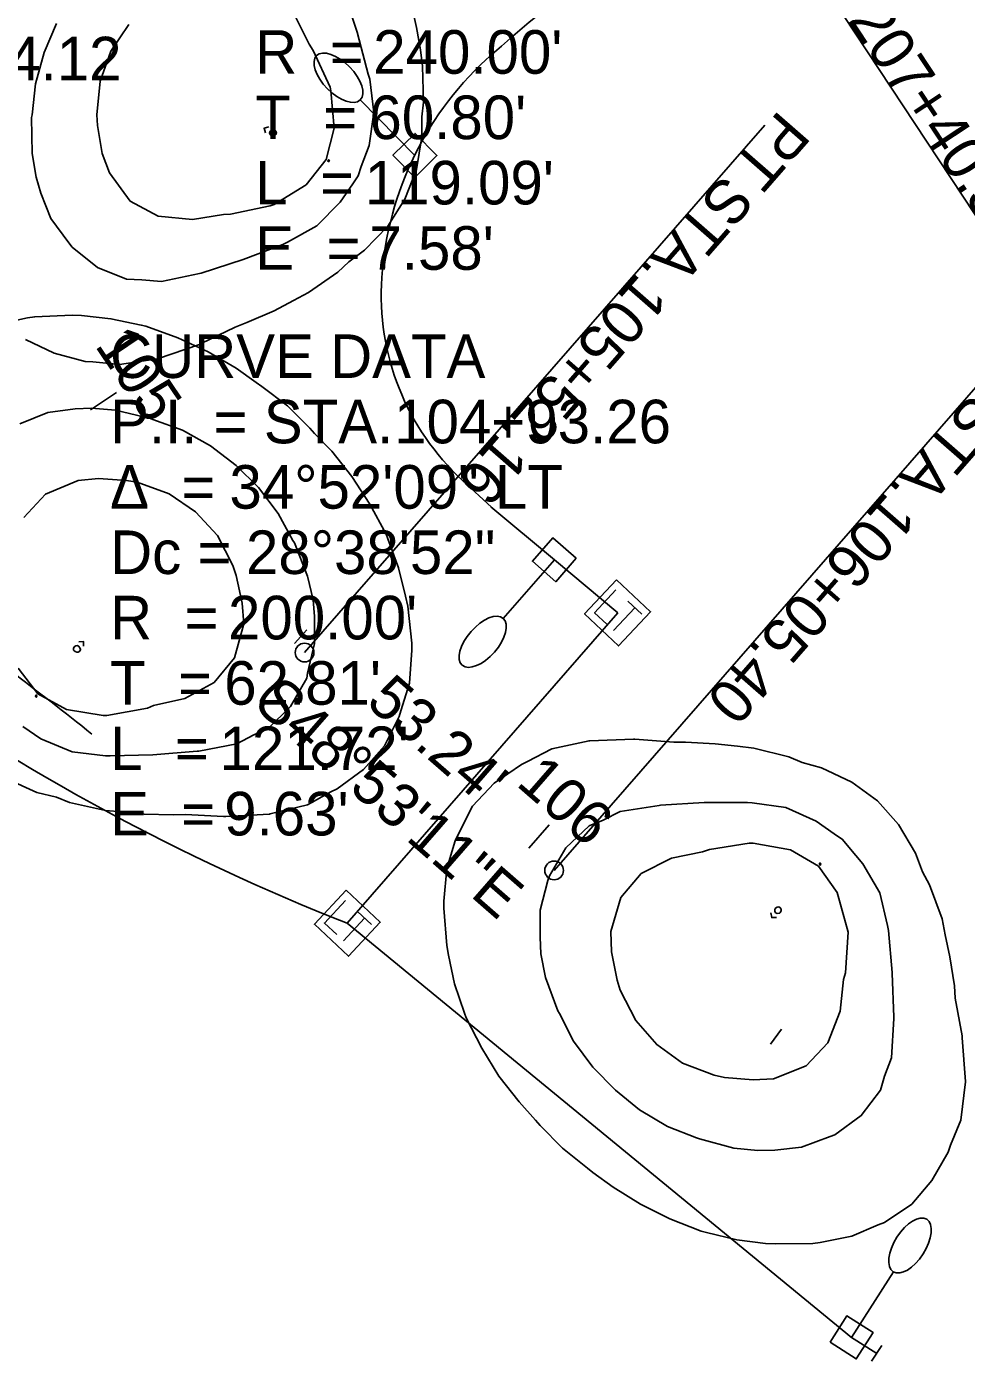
# Model space of a CAD drawing. Extents: x 1598538 to 1602183, y 285823 to 288192.
# Drawn here: x 1601032.3 to 1601183.3, y 286455.4 to 286669.9 of the extents above; entities that cross this region are included whole.
import ezdxf

# ---------------------------------------------------------------- set-up
doc = ezdxf.new("R2010")
doc.units = 0
for name, color, linetype in [('CM_Corridor_Conceptual', 7, 'Continuous'), ('CM_Corridor_Range_Conceptual', 7, 'Continuous'), ('Default', 7, 'Continuous'), ('MD_P_AGB_B', 7, 'Continuous'), ('PV_P_Curb', 7, 'Continuous'), ('PV_P_EOP', 7, 'Continuous'), ('RW_P_Esmt_LA', 7, 'Continuous'), ('RW_P_Esmt_SH', 7, 'Continuous'), ('RW_P_Esmt_TMP', 7, 'Continuous'), ('RW_P_Fee_RW', 7, 'Continuous')]:
    doc.layers.add(name, color=color, linetype=linetype)

msp = doc.modelspace()

# ---------------------------------------------------------------- linework, layer by layer
at = {"layer": 'Default'}
for points in [[(1601037.05, 286670.4), (1601035.05, 286665.71), (1601033.67, 286660.68), (1601033.17, 286655.71), (1601033.05, 286655.27), (1601033.17, 286649.52), (1601033.8, 286645.71), (1601034.55, 286643.11), (1601036.17, 286639.08), (1601039.05, 286635.15), (1601039.55, 286634.46), (1601043.67, 286631.21), (1601048.3, 286629.3), (1601050.8, 286629.21), (1601053.92, 286628.93), (1601060.05, 286630.24), (1601060.3, 286630.27), (1601067.05, 286632.46), (1601067.05, 286632.46), (1601073.42, 286634.9), (1601074.17, 286635.24), (1601078.92, 286637.86), (1601082.67, 286641.68), (1601084.67, 286644.65), (1601085.55, 286645.93), (1601086.05, 286647.43), (1601087.3, 286650.77), (1601088.05, 286656.08), (1601087.42, 286661.43), (1601087.17, 286662.24), (1601085.42, 286668.8), (1601085.42, 286668.86), (1601083.17, 286675.58)], [(1601032.05, 286619.61), (1601036.67, 286617.4), (1601041.67, 286616.11), (1601042.92, 286616.05), (1601047.17, 286615.58), (1601053.3, 286616.52), (1601053.3, 286616.52), (1601060.05, 286618.83), (1601060.3, 286618.96), (1601065.8, 286621.61), (1601067.67, 286622.33), (1601072.05, 286624.21), (1601075.17, 286625.9), (1601077.55, 286627.15), (1601082.3, 286630.43), (1601084.05, 286632.08), (1601086.55, 286633.99), (1601090.3, 286637.83), (1601093.05, 286642.15), (1601094.92, 286646.96), (1601095.8, 286652.21), (1601095.8, 286655.4), (1601096.05, 286657.77), (1601095.92, 286663.55), (1601095.55, 286666.18), (1601094.92, 286669.74), (1601093.92, 286674.33)], [(1601048.67, 286670.24), (1601045.8, 286665.96), (1601044.05, 286661.15), (1601043.55, 286655.71), (1601043.67, 286653.99), (1601044.42, 286649.52), (1601045.55, 286646.4), (1601048.92, 286641.86), (1601053.42, 286639.43), (1601058.92, 286638.9), (1601063.92, 286639.71), (1601065.05, 286639.77), (1601071.42, 286641.11), (1601072.05, 286641.33), (1601077.17, 286644.46), (1601080.42, 286648.52), (1601081.67, 286653.58), (1601081.17, 286659.55), (1601081.05, 286660.15), (1601078.3, 286666.08), (1601077.67, 286667.05), (1601075.42, 286671.55)], [(1601070.67, 286652.83), (1601070.42, 286653.55), (1601071.17, 286653.8)], [(1601071.42, 286653.08), (1601071.3, 286652.8), (1601071.3, 286652.8), (1601071.42, 286653.08), (1601071.42, 286653.08)], [(1601071.55, 286653.27), (1601071.42, 286653.08), (1601071.42, 286653.08), (1601071.55, 286653.27), (1601071.55, 286653.27)], [(1601072.05, 286653.3), (1601071.8, 286653.36), (1601071.8, 286653.36), (1601072.05, 286653.3), (1601072.05, 286653.3)], [(1601072.42, 286652.86), (1601072.3, 286653.11), (1601072.3, 286653.11), (1601072.42, 286652.86), (1601072.42, 286652.86)], [(1601029.05, 286549.02), (1601033.92, 286546.86), (1601037.05, 286546.08), (1601039.17, 286545.21), (1601044.92, 286543.96), (1601047.55, 286543.71), (1601051.17, 286543.36), (1601055.8, 286543.27), (1601057.8, 286543.3), (1601063.92, 286542.99), (1601064.3, 286542.99), (1601071.3, 286543.36), (1601071.42, 286543.4), (1601077.42, 286544.86), (1601081.17, 286546.93), (1601082.17, 286547.43), (1601086.42, 286550.55), (1601089.8, 286554.33), (1601092.17, 286559.05), (1601092.42, 286559.96), (1601093.8, 286564.43), (1601094.17, 286569.71), (1601094.17, 286570.83), (1601093.55, 286576.8), (1601093.17, 286578.36), (1601092.05, 286582.93), (1601090.3, 286587.58), (1601090.05, 286588.36), (1601087.42, 286593.18), (1601084.55, 286597.61), (1601081.3, 286601.68), (1601078.55, 286604.52), (1601077.8, 286605.4), (1601074.17, 286608.96), (1601070.05, 286612.05), (1601069.17, 286612.71), (1601065.92, 286615.02), (1601061.42, 286617.65), (1601056.55, 286619.9), (1601051.42, 286621.74), (1601050.67, 286621.93), (1601045.8, 286622.96), (1601041.05, 286623.46), (1601039.55, 286623.52), (1601033.55, 286623.27), (1601032.42, 286623.08), (1601027.17, 286621.96)], [(1601031.67, 286557.46), (1601034.55, 286555.46), (1601039.55, 286553.36), (1601044.92, 286552.74), (1601045.67, 286552.71), (1601052.55, 286552.9), (1601052.55, 286552.9), (1601059.67, 286553.46), (1601059.92, 286553.49), (1601066.05, 286554.65), (1601068.8, 286556.08), (1601071.05, 286557.08), (1601074.67, 286560.68), (1601077.3, 286565.21), (1601077.42, 286566.02), (1601078.55, 286570.77), (1601078.55, 286575.11), (1601078.3, 286577.8), (1601077.42, 286581.58), (1601075.3, 286586.93), (1601075.05, 286587.3), (1601072.67, 286591.68), (1601069.55, 286595.83), (1601065.92, 286599.4), (1601061.8, 286602.52), (1601057.3, 286605.05), (1601052.55, 286606.77), (1601052.17, 286606.93), (1601046.55, 286608.27), (1601042.67, 286608.58), (1601040.05, 286608.46), (1601035.67, 286607.9), (1601031.17, 286606.08)], [(1601030.92, 286566.83), (1601034.05, 286562.68), (1601038.67, 286560.15), (1601044.55, 286559.21), (1601045.17, 286559.21), (1601051.67, 286560.4), (1601052.67, 286560.8), (1601057.67, 286561.96), (1601062.42, 286564.52), (1601065.67, 286568.46), (1601067.17, 286573.96), (1601066.92, 286577.24), (1601065.92, 286581.71), (1601065.42, 286583.33), (1601062.92, 286588.15), (1601059.42, 286591.93), (1601055.17, 286594.83), (1601050.05, 286596.68), (1601048.3, 286596.96), (1601043.8, 286597.27), (1601040.55, 286596.99), (1601035.3, 286594.77), (1601031.8, 286591.02)], [(1601040.17, 286570.4), (1601039.92, 286570.24), (1601039.92, 286570.24), (1601040.17, 286570.4), (1601040.17, 286570.4)], [(1601040.05, 286569.49), (1601040.3, 286569.36), (1601040.3, 286569.36), (1601040.05, 286569.49), (1601040.05, 286569.49)], [(1601040.55, 286569.4), (1601040.8, 286569.55), (1601040.8, 286569.55), (1601040.55, 286569.4), (1601040.55, 286569.4)], [(1601040.67, 286571.05), (1601041.42, 286571.08), (1601041.42, 286570.36)], [(1601033.8, 286562.52), (1601033.67, 286562.33), (1601033.67, 286562.33), (1601033.8, 286562.52), (1601033.8, 286562.52)], [(1601033.92, 286562.33), (1601033.8, 286562.52), (1601033.8, 286562.52), (1601033.92, 286562.33), (1601033.92, 286562.33)], [(1601159.8, 286535.15), (1601159.92, 286535.33), (1601159.92, 286535.33), (1601159.8, 286535.15), (1601159.8, 286535.15)], [(1601152.8, 286526.77), (1601152.05, 286526.74), (1601151.92, 286527.49)]]:
    msp.add_lwpolyline(points, dxfattribs=at)
for points in [[(1601071.92, 286652.3), (1601072.17, 286652.4), (1601072.3, 286652.58), (1601072.42, 286652.86), (1601072.3, 286653.11), (1601072.05, 286653.3), (1601071.8, 286653.36), (1601071.55, 286653.27), (1601071.42, 286653.08), (1601071.3, 286652.8), (1601071.42, 286652.55), (1601071.67, 286652.36)], [(1601071.92, 286652.3), (1601072.17, 286652.4), (1601072.3, 286652.58), (1601072.42, 286652.86), (1601072.3, 286653.11), (1601072.05, 286653.3), (1601071.8, 286653.36), (1601071.55, 286653.27), (1601071.42, 286653.08), (1601071.3, 286652.8), (1601071.42, 286652.55), (1601071.67, 286652.36)], [(1601071.8, 286653.36), (1601071.55, 286653.27), (1601071.55, 286653.27), (1601071.8, 286653.36)], [(1601072.3, 286653.11), (1601072.05, 286653.3), (1601072.05, 286653.3), (1601072.3, 286653.11)], [(1601071.3, 286652.8), (1601071.42, 286652.55), (1601071.42, 286652.55), (1601071.3, 286652.8)], [(1601071.42, 286652.55), (1601071.67, 286652.36), (1601071.67, 286652.36), (1601071.42, 286652.55)], [(1601071.67, 286652.36), (1601071.92, 286652.3), (1601071.92, 286652.3), (1601071.67, 286652.36)], [(1601071.92, 286652.3), (1601072.17, 286652.4), (1601072.17, 286652.4), (1601071.92, 286652.3)], [(1601072.17, 286652.4), (1601072.3, 286652.58), (1601072.3, 286652.58), (1601072.17, 286652.4)], [(1601072.3, 286652.58), (1601072.42, 286652.86), (1601072.42, 286652.86), (1601072.3, 286652.58)], [(1601080.8, 286648.18), (1601080.92, 286648.4), (1601080.8, 286648.49), (1601080.67, 286648.27)], [(1601080.8, 286648.18), (1601080.92, 286648.4), (1601080.8, 286648.49), (1601080.67, 286648.27)], [(1601080.8, 286648.49), (1601080.67, 286648.27), (1601080.67, 286648.27), (1601080.8, 286648.49)], [(1601080.67, 286648.27), (1601080.8, 286648.18), (1601080.8, 286648.18), (1601080.67, 286648.27)], [(1601080.92, 286648.4), (1601080.8, 286648.49), (1601080.8, 286648.49), (1601080.92, 286648.4)], [(1601080.8, 286648.18), (1601080.92, 286648.4), (1601080.92, 286648.4), (1601080.8, 286648.18)], [(1601039.8, 286569.99), (1601039.8, 286569.71), (1601040.05, 286569.49), (1601040.3, 286569.36), (1601040.55, 286569.4), (1601040.8, 286569.55), (1601040.92, 286569.8), (1601040.8, 286570.08), (1601040.67, 286570.3), (1601040.42, 286570.43), (1601040.17, 286570.4), (1601039.92, 286570.24)], [(1601039.8, 286569.99), (1601039.8, 286569.71), (1601040.05, 286569.49), (1601040.3, 286569.36), (1601040.55, 286569.4), (1601040.8, 286569.55), (1601040.92, 286569.8), (1601040.8, 286570.08), (1601040.67, 286570.3), (1601040.42, 286570.43), (1601040.17, 286570.4), (1601039.92, 286570.24)], [(1601039.92, 286570.24), (1601039.8, 286569.99), (1601039.8, 286569.99), (1601039.92, 286570.24)], [(1601039.8, 286569.99), (1601039.8, 286569.71), (1601039.8, 286569.71), (1601039.8, 286569.99)], [(1601039.8, 286569.71), (1601040.05, 286569.49), (1601040.05, 286569.49), (1601039.8, 286569.71)], [(1601040.42, 286570.43), (1601040.17, 286570.4), (1601040.17, 286570.4), (1601040.42, 286570.43)], [(1601040.67, 286570.3), (1601040.42, 286570.43), (1601040.42, 286570.43), (1601040.67, 286570.3)], [(1601040.8, 286570.08), (1601040.67, 286570.3), (1601040.67, 286570.3), (1601040.8, 286570.08)], [(1601040.92, 286569.8), (1601040.8, 286570.08), (1601040.8, 286570.08), (1601040.92, 286569.8)], [(1601040.8, 286569.55), (1601040.92, 286569.8), (1601040.92, 286569.8), (1601040.8, 286569.55)], [(1601040.3, 286569.36), (1601040.55, 286569.4), (1601040.55, 286569.4), (1601040.3, 286569.36)], [(1601033.67, 286562.33), (1601033.8, 286562.15), (1601033.92, 286562.33), (1601033.8, 286562.52)], [(1601033.67, 286562.33), (1601033.8, 286562.15), (1601033.92, 286562.33), (1601033.8, 286562.52)], [(1601033.67, 286562.33), (1601033.8, 286562.15), (1601033.8, 286562.15), (1601033.67, 286562.33)], [(1601033.8, 286562.15), (1601033.92, 286562.33), (1601033.92, 286562.33), (1601033.8, 286562.15)], [(1601101.55, 286539.99), (1601101.17, 286539.08), (1601099.8, 286534.65), (1601099.3, 286529.4), (1601099.3, 286528.27), (1601099.8, 286522.27), (1601100.05, 286520.71), (1601101.05, 286516.11), (1601102.67, 286511.4), (1601102.92, 286510.61), (1601105.42, 286505.74), (1601108.17, 286501.24), (1601111.42, 286497.11), (1601114.05, 286494.21), (1601114.8, 286493.33), (1601118.42, 286489.68), (1601122.42, 286486.46), (1601123.3, 286485.8), (1601126.55, 286483.43), (1601130.92, 286480.71), (1601135.67, 286478.33), (1601140.67, 286476.36), (1601141.55, 286476.15), (1601146.42, 286474.99), (1601151.05, 286474.4), (1601152.67, 286474.3), (1601158.67, 286474.4), (1601159.8, 286474.55), (1601164.92, 286475.55), (1601169.17, 286477.4), (1601170.17, 286477.77), (1601174.55, 286480.68), (1601177.8, 286484.52), (1601180.42, 286489.05), (1601180.8, 286490.18), (1601182.42, 286494.18), (1601183.17, 286500.33), (1601183.17, 286500.4), (1601182.67, 286507.43), (1601182.67, 286507.74), (1601181.55, 286513.8), (1601181.42, 286515.77), (1601180.67, 286520.43), (1601179.92, 286523.96), (1601179.42, 286526.55), (1601177.42, 286532.02), (1601176.3, 286534.11), (1601175.17, 286537.08), (1601172.42, 286541.68), (1601169.05, 286545.52), (1601164.92, 286548.52), (1601160.05, 286550.8), (1601156.92, 286551.68), (1601154.8, 286552.58), (1601149.17, 286553.96), (1601146.55, 286554.27), (1601142.92, 286554.68), (1601138.17, 286554.9), (1601136.3, 286554.93), (1601130.05, 286555.4), (1601129.8, 286555.4), (1601122.8, 286555.15), (1601122.67, 286555.15), (1601116.67, 286553.83), (1601112.8, 286551.83), (1601111.8, 286551.36), (1601107.42, 286548.36), (1601103.92, 286544.65)], [(1601116.3, 286533.46), (1601116.05, 286532.68), (1601114.8, 286527.93), (1601114.8, 286523.61), (1601114.92, 286520.93), (1601115.67, 286517.11), (1601117.67, 286511.74), (1601117.92, 286511.33), (1601120.17, 286506.9), (1601123.3, 286502.68), (1601126.92, 286499.02), (1601130.8, 286495.83), (1601135.3, 286493.18), (1601139.92, 286491.33), (1601140.42, 286491.18), (1601145.92, 286489.71), (1601149.8, 286489.3), (1601152.55, 286489.36), (1601156.8, 286489.83), (1601161.42, 286491.55), (1601162.17, 286491.86), (1601166.42, 286494.93), (1601169.55, 286498.99), (1601170.17, 286501.27), (1601171.3, 286504.21), (1601171.67, 286510.52), (1601171.67, 286510.74), (1601171.42, 286517.8), (1601171.42, 286517.9), (1601170.8, 286524.68), (1601170.67, 286525.49), (1601169.42, 286530.74), (1601166.67, 286535.4), (1601164.42, 286538.05), (1601163.42, 286539.3), (1601162.05, 286540.18), (1601159.17, 286542.24), (1601154.3, 286544.43), (1601148.92, 286545.18), (1601148.17, 286545.24), (1601141.3, 286545.21), (1601141.17, 286545.21), (1601134.17, 286544.8), (1601133.92, 286544.77), (1601127.67, 286543.77), (1601124.92, 286542.4), (1601122.67, 286541.46), (1601118.92, 286537.96)], [(1601126.17, 286524.49), (1601126.3, 286521.21), (1601127.17, 286516.71), (1601127.67, 286515.08), (1601130.17, 286510.21), (1601133.55, 286506.33), (1601137.67, 286503.33), (1601142.8, 286501.4), (1601144.42, 286501.05), (1601149.05, 286500.65), (1601152.3, 286500.83), (1601157.55, 286502.93), (1601161.05, 286506.61), (1601163.05, 286511.71), (1601163.55, 286516.77), (1601163.92, 286517.86), (1601164.3, 286524.4), (1601164.17, 286524.99), (1601162.55, 286530.77), (1601159.55, 286535.02), (1601155.05, 286537.61), (1601149.05, 286538.71), (1601148.42, 286538.71), (1601142.05, 286537.68), (1601140.92, 286537.3), (1601135.92, 286536.27), (1601131.05, 286533.83), (1601127.8, 286529.96)], [(1601159.92, 286535.33), (1601159.8, 286535.52), (1601159.67, 286535.33), (1601159.8, 286535.15)], [(1601159.92, 286535.33), (1601159.8, 286535.52), (1601159.67, 286535.33), (1601159.8, 286535.15)], [(1601159.8, 286535.52), (1601159.67, 286535.33), (1601159.67, 286535.33), (1601159.8, 286535.52)], [(1601159.67, 286535.33), (1601159.8, 286535.15), (1601159.8, 286535.15), (1601159.67, 286535.33)], [(1601159.92, 286535.33), (1601159.8, 286535.52), (1601159.8, 286535.52), (1601159.92, 286535.33)], [(1601153.55, 286527.8), (1601153.55, 286528.08), (1601153.42, 286528.33), (1601153.17, 286528.46), (1601152.92, 286528.43), (1601152.67, 286528.27), (1601152.55, 286528.05), (1601152.55, 286527.77), (1601152.67, 286527.52), (1601152.92, 286527.4), (1601153.3, 286527.43), (1601153.42, 286527.58)], [(1601153.55, 286527.8), (1601153.55, 286528.08), (1601153.42, 286528.33), (1601153.17, 286528.46), (1601152.92, 286528.43), (1601152.67, 286528.27), (1601152.55, 286528.05), (1601152.55, 286527.77), (1601152.67, 286527.52), (1601152.92, 286527.4), (1601153.3, 286527.43), (1601153.42, 286527.58)], [(1601152.67, 286528.27), (1601152.55, 286528.05), (1601152.55, 286528.05), (1601152.67, 286528.27)], [(1601152.55, 286528.05), (1601152.55, 286527.77), (1601152.55, 286527.77), (1601152.55, 286528.05)], [(1601152.55, 286527.77), (1601152.67, 286527.52), (1601152.67, 286527.52), (1601152.55, 286527.77)], [(1601152.92, 286528.43), (1601152.67, 286528.27), (1601152.67, 286528.27), (1601152.92, 286528.43)], [(1601152.67, 286527.52), (1601152.92, 286527.4), (1601152.92, 286527.4), (1601152.67, 286527.52)], [(1601153.17, 286528.46), (1601152.92, 286528.43), (1601152.92, 286528.43), (1601153.17, 286528.46)], [(1601152.92, 286527.4), (1601153.3, 286527.43), (1601153.3, 286527.43), (1601152.92, 286527.4)], [(1601153.42, 286528.33), (1601153.17, 286528.46), (1601153.17, 286528.46), (1601153.42, 286528.33)], [(1601153.3, 286527.43), (1601153.42, 286527.58), (1601153.42, 286527.58), (1601153.3, 286527.43)], [(1601153.55, 286528.08), (1601153.42, 286528.33), (1601153.42, 286528.33), (1601153.55, 286528.08)], [(1601153.42, 286527.58), (1601153.55, 286527.8), (1601153.55, 286527.8), (1601153.42, 286527.58)], [(1601153.55, 286527.8), (1601153.55, 286528.08), (1601153.55, 286528.08), (1601153.55, 286527.8)]]:
    msp.add_lwpolyline(points, close=True, dxfattribs=at)
msp.add_arc((1600554.3, 285941.06), 785.5, 51.55039, 53.98502, dxfattribs=at)
at = {"layer": 'MD_P_AGB_B'}
for p, q in [((1601042.53, 286608.33), (1601046.68, 286611.12)), ((1601075.32, 286570.76), (1601077.31, 286572.99)), ((1601112.98, 286537.87), (1601116.27, 286541.64)), ((1601151.83, 286506.42), (1601153.6, 286508.83))]:
    msp.add_line(p, q, dxfattribs=at)
at = {"layer": 'PV_P_Curb'}
for p, q in [((1601124.67, 286730.7), (1601186.62, 286636.79)), ((1601076.94, 286569.32), (1601150.91, 286654.08)), ((1601117.05, 286534.32), (1601191.02, 286619.08))]:
    msp.add_line(p, q, dxfattribs=at)
for centre in [(1601076.94, 286569.32), (1601117.05, 286534.32)]:
    msp.add_circle(centre, 1.5, dxfattribs=at)
at = {"layer": 'RW_P_Esmt_LA'}
for p, q in [((1601094.66, 286649.2), (1601085.88, 286658.11)), ((1601117.09, 286584.24), (1601108.87, 286574.82)), ((1601164.87, 286459.29), (1601171.59, 286469.84))]:
    msp.add_line(p, q, dxfattribs=at)
for points in [[(1601094.64, 286645.67), (1601091.13, 286649.23), (1601094.69, 286652.74), (1601098.2, 286649.18)], [(1601120.62, 286584.48), (1601117.33, 286580.71), (1601113.56, 286584), (1601116.85, 286587.76)], [(1601161.42, 286458.53), (1601164.1, 286462.75), (1601168.32, 286460.06), (1601165.63, 286455.84)]]:
    msp.add_lwpolyline(points, close=True, dxfattribs=at)
for centre, major_axis in [((1601082.38, 286661.67), (-3.51, 3.56)), ((1601105.58, 286571.05), (-3.29, -3.77)), ((1601174.27, 286474.05), (2.69, 4.22))]:
    msp.add_ellipse(centre, major_axis=major_axis, ratio=0.5, dxfattribs=at)
at = {"layer": 'RW_P_Esmt_SH'}
msp.add_line((1601083.81, 286525.83), (1601127.28, 286575.72), dxfattribs=at)
at = {"layer": 'RW_P_Esmt_TMP'}
for p, q in [((1601102.32, 286596.98), (1601106.98, 286592.68)), ((1601106.9, 286592.75), (1601117.09, 286584.24)), ((1601117.09, 286584.24), (1601127.28, 286575.72)), ((1601083.81, 286525.83), (1601164.87, 286459.29)), ((1601164.7, 286459.4), (1601168.91, 286456.72)), ((1601168.09, 286455.45), (1601169.72, 286457.96))]:
    msp.add_line(p, q, dxfattribs=at)
for centre, radius, start, end in [((1601373.64, 286361.68), 404.14, 122.3345, 131.265), ((1601141.72, 286626), 52.5, 131.265, 176.096), ((1601129.83, 286626.81), 40.58, 176.096, 227.3201), ((1601214.78, 286858.3), 357.34, 234.7208, 248.4986)]:
    msp.add_arc(centre, radius, start, end, dxfattribs=at)
at = {"layer": 'RW_P_Fee_RW'}
for p, q in [((1601127.26, 286575.7), (1601127.26, 286575.7)), ((1601083.81, 286525.83), (1601083.81, 286525.83))]:
    msp.add_line(p, q, dxfattribs=at)
for points in [[(1601127.08, 286581), (1601132.56, 286575.87), (1601127.43, 286570.4), (1601121.96, 286575.53)], [(1601083.63, 286531.13), (1601089.11, 286526), (1601083.98, 286520.53), (1601078.51, 286525.66)]]:
    msp.add_lwpolyline(points, close=True, dxfattribs=at)
for points in [[(1601126.98, 286579.38), (1601123.57, 286575.73), (1601125.55, 286573.87)], [(1601130.03, 286576.53), (1601126.61, 286572.88)], [(1601128.88, 286577.6), (1601131.15, 286575.48)], [(1601083.53, 286529.51), (1601080.12, 286525.86), (1601082.1, 286524)], [(1601086.58, 286526.66), (1601083.17, 286523.01)], [(1601085.43, 286527.73), (1601087.7, 286525.61)]]:
    msp.add_lwpolyline(points, dxfattribs=at)

# ---------------------------------------------------------------- texts
at = {"layer": 'CM_Corridor_Conceptual'}
for s, p in [('205+64.12', (1601003, 286661.26)), ('R  = ', (1601069.01, 286662.32)), ("240.00'", (1601087.97, 286662.32)), ('T  = ', (1601069.01, 286651.82)), ("60.80'", (1601087.36, 286651.82)), ('L  = ', (1601069.01, 286641.32)), ("119.09'", (1601086.61, 286641.32)), ('E  = ', (1601069.01, 286630.82)), ("7.58'", (1601087.36, 286630.82)), ('CURVE DATA', (1601045.67, 286613.44)), ('P.I. = STA. ', (1601045.67, 286602.94)), ('104+93.26', (1601091.34, 286602.94)), ('34°52\'09" LT', (1601064.86, 286592.44)), ('Δ  = ', (1601045.67, 286592.44)), ('Dc = ', (1601045.67, 286581.94)), ('28°38\'52"', (1601067.52, 286581.94)), ('R  = ', (1601045.67, 286571.44)), ("200.00'", (1601064.63, 286571.44)), ('T  = ', (1601045.67, 286560.94)), ("62.81'", (1601064.02, 286560.94)), ('L  = ', (1601045.67, 286550.44)), ("121.72'", (1601063.27, 286550.44)), ('E  = ', (1601045.67, 286539.94)), ("9.63'", (1601064.02, 286539.94))]:
    msp.add_text(s, height=7, dxfattribs=at).set_placement(p)
at = {"layer": 'CM_Corridor_Range_Conceptual'}
msp.add_text("53.24'", height=7, rotation=318.8864, dxfattribs=at).set_placement((1601086.59, 286561.04))
at = {"layer": 'MD_P_AGB_B'}
for s, rotation, p in [('105', 303.9428, (1601043.1, 286618.68)), ('106', 318.8864, (1601110.76, 286548.1))]:
    msp.add_text(s, height=7, rotation=rotation, dxfattribs=at).set_placement(p)
at = {"layer": 'PV_P_Curb'}
for s, rotation, p in [('207+40.57', 303.4087, (1601164.2, 286670.96)), ('PT', 228.8864, (1601153.32, 286656.68)), (' STA. ', 228.8864, (1601146.07, 286648.37)), ('105+52.16', 228.8864, (1601130.53, 286630.57)), (' STA. ', 228.8864, (1601186.01, 286613.18)), ('106+05.40', 228.8864, (1601170.48, 286595.38))]:
    msp.add_text(s, height=7, rotation=rotation, dxfattribs=at).set_placement(p)
at = {"layer": 'PV_P_EOP'}
msp.add_text('S48°53\'11"E', height=7, rotation=318.8864, dxfattribs=at).set_placement((1601068.5, 286560.76))

doc.saveas('drawing.dxf')
